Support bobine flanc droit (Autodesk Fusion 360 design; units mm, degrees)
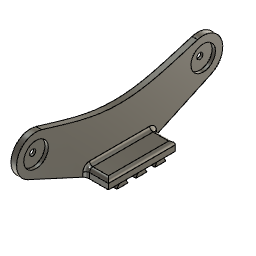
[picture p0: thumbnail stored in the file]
sketch "Esquisse1" plane through (0, 0, 0) normal (1, 0, 0) x axis (0, 1, 0)
  line L1 (30, 3.8) -> (-30, 3.8)
  line L2 (0, 13.257) -> (0, 0)
  line L3 (-4.9, 0) -> (-2.9, 3.8)
  line L4 (4.9, 0) -> (2.9, 3.8)
  line L5 (-21.9, 0) -> (-19.9, 3.8)
  line L6 (-12.1, 0) -> (-14.1, 3.8)
  line L7 (12.1, 0) -> (14.1, 3.8)
  line L8 (21.9, 0) -> (19.9, 3.8)
  line L9 (-12.1, 0) -> (-21.9, 0)
  line L10 (4.9, 0) -> (-4.9, 0)
  line L11 (21.9, 0) -> (12.1, 0)
  line L12 (75, 43.8) -> (-75, 43.8)
  line L13 (82.3227, 27.9057) -> (30, 3.8)
  line L14 (-82.3227, 27.9057) -> (-30, 3.8)
  curve K1 (70.0046, 60.5719) -> (-70.0046, 60.5719)
  curve K2 (14.2216, 45.8) -> (-14.2216, 45.8)
  line L15 (-30, 11.8) -> (-30, 3.8)
  line L16 (30, 11.8) -> (30, 3.8)
  line L17 (30, 11.8) -> (-30, 11.8)
  circle C1 centre (-75, 43.8) radius 2.7
  circle C2 centre (-75, 43.8) radius 8
  circle C3 centre (-75, 43.8) radius 17.5
  circle C4 centre (75, 43.8) radius 2.7
  circle C5 centre (75, 43.8) radius 8
  circle C6 centre (75, 43.8) radius 17.5
  circle C7 centre (0, 121.511) radius 100
  point P1 (0, 0)
  point P4 (0, 0)
  point P6 (-2.9, 3.8)
  point P7 (-4.9, 0)
  point P8 (2.9, 3.8)
  point P9 (4.9, 0)
  point P18 (-75, 43.8)
  point P20 (-75, 43.8)
  point P27 (82.3227, 27.9057)
  point P28 (-82.3227, 27.9057)
  point P29 (-70.0046, 60.5719)
  point P31 (70.0046, 60.5719)
  point P30 (0, 45.8)
  point P19 (75, 43.8)
  point P2 (-30, 3.8)
  point P3 (30, 3.8)
  horizontal L9
  parallel L1 L9
  coincident P1 P4
  perpendicular L2 L9
  coincident L1 P6
  coincident P7 L9
  symmetric L2 P6 P8
  symmetric L2 P7 P9
  coincident P1 L9
  collinear L9 L10
  collinear L10 L11
  horizontal L12
  coincident P18 P20
  concentric C1 C2
  concentric C2 C3
  symmetric L2 C1 C4
  symmetric L2 C2 C5
  symmetric L2 C3 C6
  tangent C2 C7
  tangent C5 C7
  coincident C6 P27
  tangent C6 L13
  coincident C3 P28
  tangent C3 L14
  coincident C3 P29
  coincident C6 P31
  tangent C6 K1
  tangent C3 K1
  midpoint P30 K2
  horizontal K2
  perpendicular L1 L15
  perpendicular L1 L16
  dimension "d2" distance L1 L9 = 3.8
  dimension "d3" distance L2 P6 = 2.9
  dimension "d4" distance L2 P7 = 4.9
  dimension "d9" distance P18 P19 = 150
  dimension "d10" distance P1 P18 = 75
  dimension "d11" diameter C1 = 5.4
  dimension "d12" diameter C2 = 16
  dimension "d13" diameter C3 = 35
  dimension "d14" diameter C7 = 200
  dimension "d15" distance L1 L12 = 40
  dimension "d16" distance L1 P30 = 42
  dimension "d23" distance P2 P3 = 60
  dimension "d25" distance P1 L15 = 30
  dimension "d26" distance L1 L17 = 8
  dimension "d7" R-Pattern1-uDistance = 17
  dimension "d8" R-Pattern1-vDistance = 0
extrude "Extrusion1" new body sketch "Esquisse1" profile of C1 C3 C4 C6 L13 L14 K1 L15 L16 L17 along normal blind 5
extrude "Extrusion2" add sketch "Esquisse1" profile of L1 L15 L16 L17 along normal blind 25
sketch "Esquisse2" plane through (5, 0, 0) normal (1, 0, 0) x axis (0, 1, 0)
  line L1 (-30, 11.8) -> (-30, 3.8)
  line L2 (30, 11.8) -> (-30, 11.8)
  line L3 (30, 3.8) -> (30, 11.8)
  line L4 (82.3227, 27.9057) -> (30, 3.8)
  curve K1 (-70.0046, 60.5719) -> (70.0046, 60.5719)
  line L5 (-30, 3.8) -> (-82.3227, 27.9057)
  circle C1 centre (-75, 43.8) radius 2.7
  circle C2 centre (75, 43.8) radius 2.7
  arc A1 centre (75, 43.8) radius 17.5 clockwise from (70.0046, 60.5719) to (82.3227, 27.9057)
  arc A2 centre (-75, 43.8) radius 17.5 clockwise from (-82.3227, 27.9057) to (-70.0046, 60.5719)
  circle C3 centre (-75, 43.8) radius 11
  circle C4 centre (75, 43.8) radius 11
  concentric C1 C3
  concentric C2 C4
  dimension "d34" diameter C3 = 22
  dimension "d35" diameter C4 = 22
extrude "Extrusion3" cut sketch "Esquisse2" profile of C1 C2 C3 C4 against normal blind 3
fillet "Congé2" radius 3
fillet "Congé3" radius 3
extrude "Extrusion8" add sketch "Esquisse1" profile of L11 L1 L3 L4 L5 L6 L7 L8 along normal blind 24.5
sketch "Esquisse6" plane through (0, 0, 0) normal (0, 0, -1) x axis (1, 0, 0)
  line L1 (0, -4.9) -> (0, 4.9)
  line L2 (24.5, -4.9) -> (0, -4.9)
  line L3 (24.5, 4.9) -> (24.5, -4.9)
  line L4 (0, 4.9) -> (24.5, 4.9)
  line L5 (0, -4.9) -> (0, 4.9)
  circle C1 centre (12.5, 0) radius 1.4
  point P6 (12.5, 0)
  dimension "d62" diameter C1 = 2.8
  dimension "d63" distance L4 P6 = 4.9
  dimension "d64" distance P6 L5 = 12.5
extrude "Extrusion9" cut sketch "Esquisse6" profile of C1 against normal blind 10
